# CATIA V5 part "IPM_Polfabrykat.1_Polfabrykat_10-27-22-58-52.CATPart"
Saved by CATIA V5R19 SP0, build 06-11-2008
Part number: IPM_Polfabrykat.1_Polfabrykat10-27-22-58-52
Bounding box of the stored display mesh (mm): x -70 to 70, y 0 to 0, z -35.352 to 40.648
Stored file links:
  D:\POBO\podręcznik\ProcesTechnologiczny\Toczenie-CD\IPM_Polfabrykat.1_Polfabrykat_10-27-22-58-52.CATPart
  D:\POBO\podręcznik\ProcesTechnologiczny\Toczenie-CD\Polfabrykat.CATPart
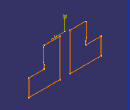
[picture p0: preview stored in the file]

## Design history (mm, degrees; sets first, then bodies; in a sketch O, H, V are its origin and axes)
Body1 (main body)
  Body2 "ImportedStock"
    Body3 "Polfabrykat"
      Solid1: linked copy from another document
    Add1: tool Body3
  Add2: tool Body2
  Body4 "Rough Turning.1"
    Plane1: stored without definition
    Sketch1 on Plane1, origin (0, 0, 40.6477), H (0, 0, 1), V (1, 0, 0)
      axis line L1 through (0, 0) direction (1, 0)
      line L2 (-0.6903, 0) -> (6.0378, 4.2284)
      point P1 (-0.6903, 0)
      point P2 (6.0378, 4.2284)
      line L3 (6.0378, 4.2284) -> (6.2499, 4.4405)
      point P3 (6.0378, 4.2284)
      point P4 (6.2499, 4.4405)
      arc A1 centre (5.6842, 5.0062) radius 0.8 from (6.2499, 4.4405) to (6.4831, 4.9643) ccw
      point P5 (6.2499, 4.4405)
      point P6 (6.4831, 4.9643)
      line L4 (6.4831, 4.9643) -> (6.9566, 13.9987)
      point P7 (6.4831, 4.9643)
      point P8 (6.9566, 13.9987)
      arc A2 centre (6.2448, 14.0551) radius 0.7141 from (6.9566, 13.9987) to (6.7456, 14.5641) ccw
      point P9 (6.9566, 13.9987)
      point P10 (6.7456, 14.5641)
      line L5 (6.7456, 14.5641) -> (6.7456, 86.6284)
      point P11 (6.7456, 14.5641)
      point P12 (6.7456, 86.6284)
      arc A3 centre (5.9456, 86.6284) radius 0.8 from (6.7456, 86.6284) to (5.5216, 87.3069) ccw
      point P13 (6.7456, 86.6284)
      point P14 (5.5216, 87.3069)
      line L6 (5.5216, 87.3069) -> (-2.1505, 82.5128)
      point P15 (5.5216, 87.3069)
      point P16 (-2.1505, 82.5128)
      arc A4 centre (-1.7265, 81.8344) radius 0.8 from (-2.1505, 82.5128) to (-2.5254, 81.8762) ccw
      point P17 (-2.1505, 82.5128)
      point P18 (-2.5254, 81.8762)
      line L7 (-2.5254, 81.8762) -> (-3, 72.8)
      point P19 (-2.5254, 81.8762)
      point P20 (-3, 72.8)
      line L8 (-3, 72.8) -> (-3, 0)
      point P21 (-3, 72.8)
      point P22 (-3, 0)
      line L9 (-3, 0) -> (-0.6903, 0)
      point P23 (-3, 0)
      point P24 (-0.6903, 0)
      coincidence: P1 P24, P2 P3, P4 P5, P6 P7, P8 P9, P10 P11, P12 P13, P14 P15, P16 P17, P18 P19, P20 P21, P22 P23
    Shaft1: profile Sketch1, axis Sketch1.L1, angle 360
  Remove1: tool Body4
  Body5 "Rough Turning.2"
    Plane2: stored without definition
    Sketch2 on Plane2, origin (0, 0, 40.6477), H (0, 0, 1), V (1, 0, 0)
      axis line L1 through (0, 0) direction (1, 0)
      line L2 (0.8, 39.8787) -> (0.8, 70.8)
      point P1 (0.8, 39.8787)
      point P2 (0.8, 70.8)
      line L3 (0.8, 70.8) -> (-43, 70.8)
      point P3 (0.8, 70.8)
      point P4 (-43, 70.8)
      line L4 (-43, 70.8) -> (-43, 40.8)
      point P5 (-43, 70.8)
      point P6 (-43, 40.8)
      arc A1 centre (-42.2, 40.8) radius 0.8 from (-43, 40.8) to (-42.2, 40) ccw
      point P7 (-43, 40.8)
      point P8 (-42.2, 40)
      line L5 (-42.2, 40) -> (-36.636, 40)
      point P9 (-42.2, 40)
      point P10 (-36.636, 40)
      line L6 (-36.636, 40) -> (-36.3624, 40.0482)
      point P11 (-36.636, 40)
      point P12 (-36.3624, 40.0482)
      line L7 (-36.3624, 40.0482) -> (-31, 42)
      point P13 (-36.3624, 40.0482)
      point P14 (-31, 42)
      line L8 (-31, 42) -> (-5.1213, 42)
      point P15 (-31, 42)
      point P16 (-5.1213, 42)
      line L9 (-5.1213, 42) -> (-3.2343, 40.113)
      point P17 (-5.1213, 42)
      point P18 (-3.2343, 40.113)
      arc A2 centre (-2.6686, 40.6787) radius 0.8 from (-3.2343, 40.113) to (-2.6686, 39.8787) ccw
      point P19 (-3.2343, 40.113)
      point P20 (-2.6686, 39.8787)
      line L10 (-2.6686, 39.8787) -> (0.8, 39.8787)
      point P21 (-2.6686, 39.8787)
      point P22 (0.8, 39.8787)
      coincidence: P1 P22, P2 P3, P4 P5, P6 P7, P8 P9, P10 P11, P12 P13, P14 P15, P16 P17, P18 P19, P20 P21
    Shaft2: profile Sketch2, axis Sketch2.L1, angle 360
  Remove2: tool Body5
  Body6 "Drilling.1"
    Plane3: stored without definition
    Sketch3 on Plane3, origin (0, 0, 40.6477), H (1, 0, 0), V (0, 0, 1)
      axis line L1 through (0, 0) direction (0, 1)
      line L2 (0, 51) -> (0, -85.7735)
      point P1 (0, 51)
      point P2 (0, -85.7735)
      line L3 (0, -85.7735) -> (10, -80)
      point P3 (0, -85.7735)
      point P4 (10, -80)
      line L4 (10, -80) -> (10, 51)
      point P5 (10, -80)
      point P6 (10, 51)
      line L5 (10, 51) -> (0, 51)
      point P7 (10, 51)
      point P8 (0, 51)
      coincidence: P1 P8, P2 P3, P4 P5, P6 P7
    Shaft3: profile Sketch3, axis Sketch3.L1, angle 360
  Remove3: tool Body6
  Body7 "Rough Turning.3"
    Plane4: stored without definition
    Sketch4 on Plane4, origin (0, 0, 40.6477), H (0, 0, 1), V (1, 0, 0)
      axis line L1 through (0, 0) direction (1, 0)
      line L2 (-2.6, 26) -> (-22.6, 26)
      point P1 (-2.6, 26)
      point P2 (-22.6, 26)
      arc A1 centre (-22.6, 25.6) radius 0.4 from (-22.6, 26) to (-23, 25.6) ccw
      point P3 (-22.6, 26)
      point P4 (-23, 25.6)
      line L3 (-23, 25.6) -> (-23, 9.6)
      point P5 (-23, 25.6)
      point P6 (-23, 9.6)
      line L4 (-23, 9.6) -> (-2.6, 9.6)
      point P7 (-23, 9.6)
      point P8 (-2.6, 9.6)
      line L5 (-2.6, 9.6) -> (-2.6, 26)
      point P9 (-2.6, 9.6)
      point P10 (-2.6, 26)
      coincidence: P1 P10, P2 P3, P4 P5, P6 P7, P8 P9
    Shaft4: profile Sketch4, axis Sketch4.L1, angle 360
  Remove4: tool Body7
Body8 "Input Stock Body for_Rough Turning.3_22.58.58"
  Plane5 "ProfilePlane": stored without definition
  Sketch5 "Input Stock Sketch for_Rough Turning.3_22.58.58" on Plane5, origin (0, 0, 40.6477), H (0, 0, 1), V (1, 0, 0)
    line L1 (-76, 70) -> (-43, 70)
    line L2 (-43, 40.8) -> (-43, 70)
    frozenspline C1
    line L3 (-42.2, 40) -> (-36.636, 40)
    line L4 (-36.636, 40) -> (-36.3624, 40.0482)
    line L5 (-36.3624, 40.0482) -> (-31, 42)
    line L6 (-31, 42) -> (-5.1213, 42)
    line L7 (-3.2343, 40.113) -> (-5.1213, 42)
    frozenspline C2
    line L8 (-3, 10) -> (-3, 39.9505)
    line L9 (-76, 10) -> (-3, 10)
    line L10 (-76, 10) -> (-76, 70)
    line L11 (-76, -70) -> (-43, -70)
    line L12 (-76, -70) -> (-76, -10)
    line L13 (-76, -10) -> (-3, -10)
    line L14 (-3, -39.9505) -> (-3, -10)
    frozenspline C3
    line L15 (-3.2343, -40.113) -> (-5.1213, -42)
    line L16 (-31, -42) -> (-5.1213, -42)
    line L17 (-36.3624, -40.0482) -> (-31, -42)
    line L18 (-36.636, -40) -> (-36.3624, -40.0482)
    line L19 (-42.2, -40) -> (-36.636, -40)
    frozenspline C4
    line L20 (-43, -70) -> (-43, -40.8)
Body9 "Input Stock Body for_Groove Turning.1_19.34.16"
  Plane6 "ProfilePlane": stored without definition
  Sketch6 "Input Stock Sketch for_Groove Turning.1_19.34.16" on Plane6, origin (0, 0, 40.6477), H (0, 0, 1), V (1, 0, 0)
    line L1 (-76, 70) -> (-43, 70)
    line L2 (-43, 40.8) -> (-43, 70)
    frozenspline C1
    line L3 (-42.2, 40) -> (-36.636, 40)
    line L4 (-36.636, 40) -> (-36.3624, 40.0482)
    line L5 (-36.3624, 40.0482) -> (-31, 42)
    line L6 (-31, 42) -> (-5.1213, 42)
    line L7 (-3.2343, 40.113) -> (-5.1213, 42)
    frozenspline C2
    line L8 (-3, 26) -> (-3, 39.9505)
    line L9 (-22.6, 26) -> (-3, 26)
    frozenspline C3
    line L10 (-23, 10) -> (-23, 25.6)
    line L11 (-76, 10) -> (-23, 10)
    line L12 (-76, 10) -> (-76, 70)
    line L13 (-76, -70) -> (-43, -70)
    line L14 (-76, -70) -> (-76, -10)
    line L15 (-76, -10) -> (-23, -10)
    line L16 (-23, -25.6) -> (-23, -10)
    frozenspline C4
    line L17 (-22.6, -26) -> (-3, -26)
    line L18 (-3, -39.9505) -> (-3, -26)
    frozenspline C5
    line L19 (-3.2343, -40.113) -> (-5.1213, -42)
    line L20 (-31, -42) -> (-5.1213, -42)
    line L21 (-36.3624, -40.0482) -> (-31, -42)
    line L22 (-36.636, -40) -> (-36.3624, -40.0482)
    line L23 (-42.2, -40) -> (-36.636, -40)
    frozenspline C6
    line L24 (-43, -70) -> (-43, -40.8)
